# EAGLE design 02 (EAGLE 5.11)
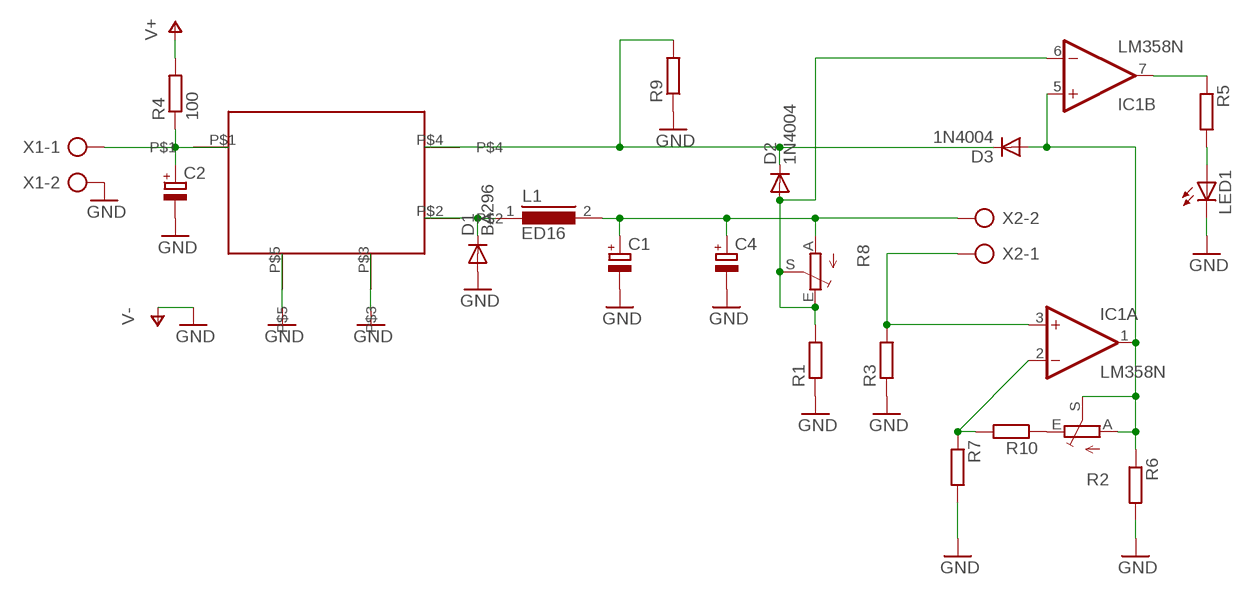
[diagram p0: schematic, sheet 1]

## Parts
C1  CPOL-EUE5-13  [E5-13]
C2  CPOL-EUE5-13  [E5-13]
C4  CPOL-EUE5-13  [E5-13]
D1  BA296  [P2-15]
D2  1N4004  [DO41-10]
D3  1N4004  [DO41-10]
IC1  LM358N  [DIL08]
L1  ED16  [ED16]
LED1  LED3MM  [LED3MM]
R1  R-EU_0207/10  [0207/10]
R2  TRIM_EU-B25P  [B25P]
R3  R-EU_0411/15  [0411/15]
R4  100  R-EU_0207/10  [0207/10]
R5  R-EU_0207/10  [0207/10]
R6  R-EU_0207/10  [0207/10]
R7  R-EU_0207/10  [0207/10]
R8  TRIM_EU-B25P  [B25P]
R9  R-EU_0204/2V  [0204V]
R10  R-EU_0204/7  [0204/7]
U$1  01  [TO220-5_STAGGERED]
X1  AK300/2  [AK300/2]
X2  AK300/2  [AK300/2]

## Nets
N$1: C2.+ R4.1 U$1.P$1 X1.1
N$2: D1.C L1.1 U$1.P$2
N$3: C1.+ C4.+ L1.2 R8.A X2.2
N$4: D2.A IC1.6(B:-IN) R1.2 R8.E R8.S
N$5: IC1.3(A:+IN) R3.2 X2.1
N$6: D2.C D3.C R9.2 U$1.P$4
N$7: IC1.2(A:-IN) R7.1 R10.2
N$8: D3.A IC1.1(A:OUT) IC1.5(B:+IN) R2.A R2.S R6.1
N$9: C1.- C2.- C4.- D1.A LED1.K(C) R1.1 R3.1 R6.2 R7.2 R9.1 U$1.P$3 U$1.P$5 X1.2 ; supply symbol labelled GND
N$10: IC1.7(B:OUT) R5.1
N$11: LED1.A R5.2
N$12: R2.E R10.1
V+: R4.2

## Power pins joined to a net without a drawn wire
N$9: IC1.4(P:V-)
V+: IC1.8(P:V+)

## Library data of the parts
C1 C2 C4 = resistor:CPOL-EU: POLARIZED CAPACITOR, European symbol
D1 = diode:BA296: DIODE
D2 D3 = diode:1N4004: DIODE
IC1 = linear:LM358: OP AMP also LM158; LM258; LM2904 Source: http://cache.national.com/ds/LM/LM158.pdf
L1 = inductors:ED16: INDUCTOR
LED1 = led:LED: LED
R1 R3-R7 R9 R10 = resistor:R-EU_: RESISTOR, European symbol
R2 R8 = pot:TRIM_EU-: POTENTIOMETER
U$1 = to220-my:01
X1 X2 = con-ptr500:AK300/2: CONNECTOR; OC_FARNELL: unknown; OC_NEWARK: unknown

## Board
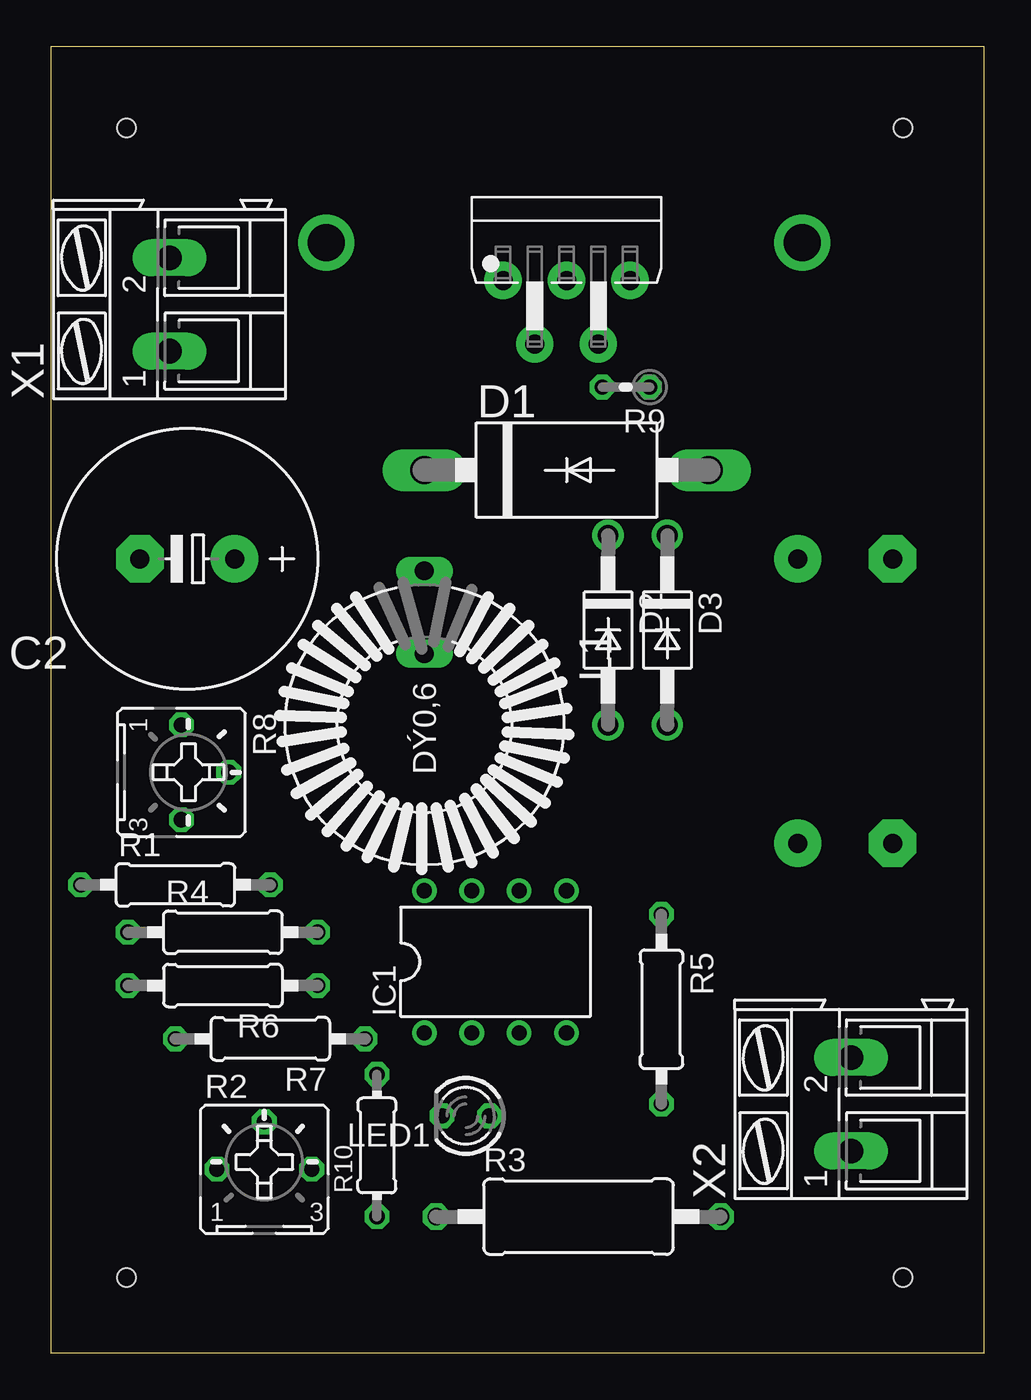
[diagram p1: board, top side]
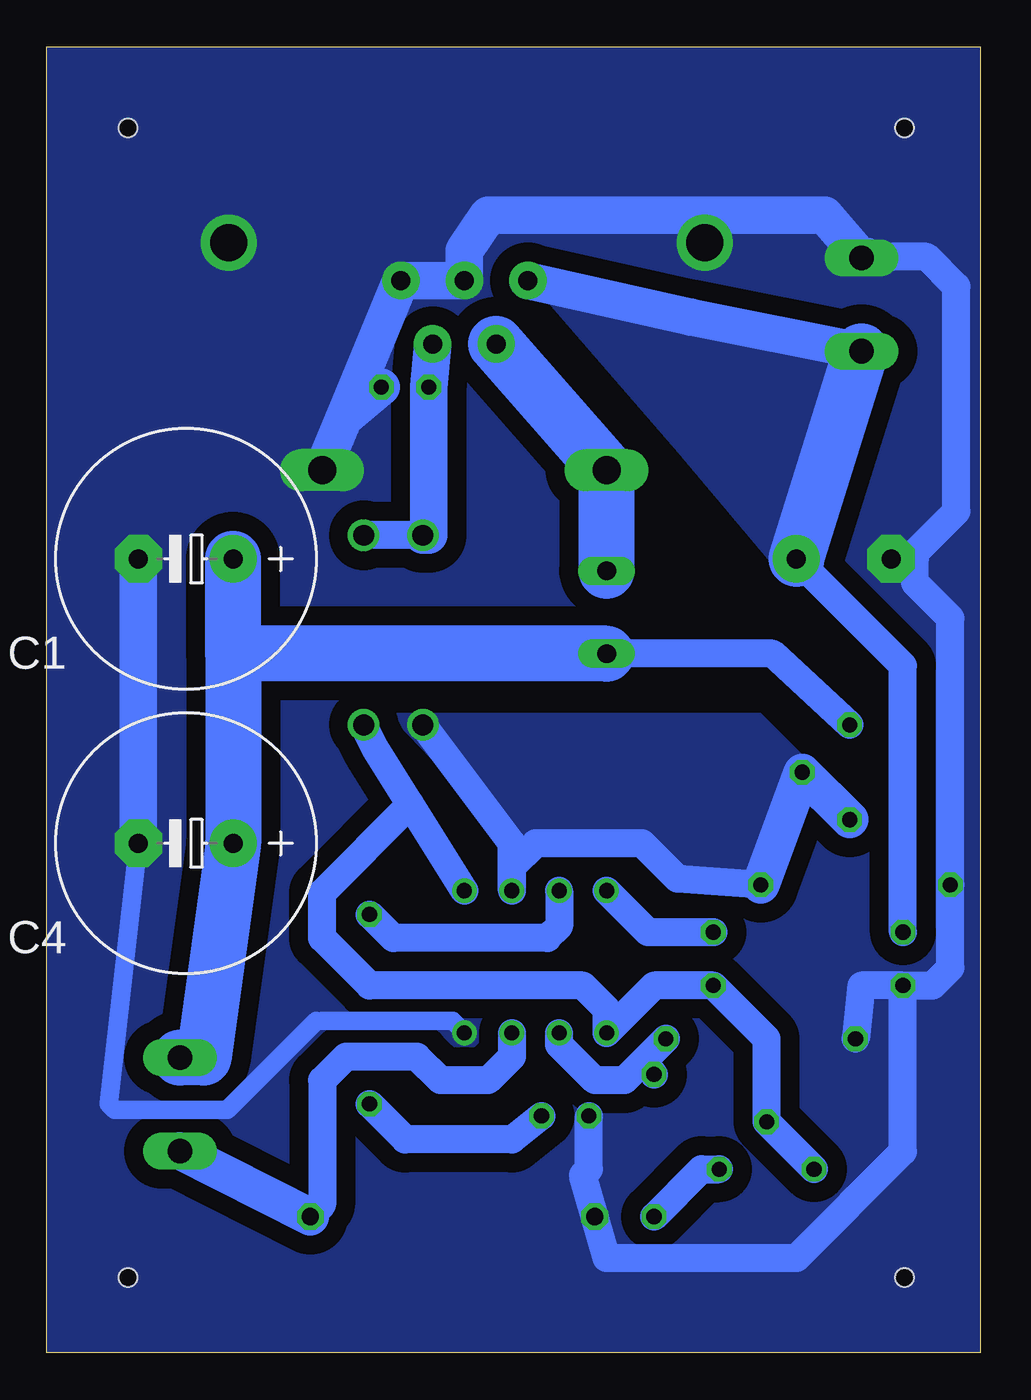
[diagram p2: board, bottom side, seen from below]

Size 50 x 70 mm. Coordinates in mm from the lower left corner, seen from the top.
Outline: 0,0 50,0 50,70 0,70 0,0
Copper layers (1*16): Top 0.035mm / dielectric 1.5mm / Bottom 0.035mm
Design rules "default *": minimum track width 20mil, minimum drill 20mil, track to track 40mil, track to pad 40mil, pad to pad 40mil, via to via 40mil, smd to smd 40mil, copper to edge 0mil, drill to drill 8mil, minimum pad ring 10mil, minimum via ring 8mil, stop-mask expansion 4mil, vias tented up to drill 0mil, thermal gap 0mil
Holes 1 mm at 45.64,4.05 4.05,4.05 4.05,65.64 45.64,65.64

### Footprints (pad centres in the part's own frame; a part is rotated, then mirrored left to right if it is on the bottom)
E5-13 = drill 1.016 pad 2.54 round: + -2.54,0 | drill 1.016 pad 2.54 octagon: - 2.54,0
P2-15 = drill 1.499 long: A 7.62,0; C -7.62,0
DO41-10 = drill 1.118 round: A 5.08,0; C -5.08,0
DIL08 = drill 0.813 pad 1.27 round: 1 -3.81,-3.81; 2 -1.27,-3.81; 3 1.27,-3.81; 4 3.81,-3.81; 5 3.81,3.81; 6 1.27,3.81; 7 -1.27,3.81; 8 -3.81,3.81
ED16 = drill 1.016 long: 1 -8.255,0; 2 -3.81,0
LED3MM = drill 0.813 octagon: A -1.27,0; K 1.27,0
0207/10 = drill 0.813 octagon: 1 -5.08,0; 2 5.08,0
B25P = drill 0.813 octagon: A -2.54,0; E 2.54,0; S 0,2.54
0411/15 = drill 0.914 octagon: 1 -7.62,0; 2 7.62,0
0204V = drill 0.813 octagon: 1 -1.27,0; 2 1.27,0
0204/7 = drill 0.813 octagon: 1 -3.81,0; 2 3.81,0
TO220-5_STAGGERED = drill 1.016 pad 2 round: P$1 -3.402,0; P$2 -1.704,-3.404; P$3 -0.002,0; P$4 1.7,-3.404; P$5 3.402,0
AK300/2 = drill 1.321 long: 1 -2.515,0; 2 2.489,0

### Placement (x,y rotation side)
C1  42.55,42.55 180 bottom
C2  7.3,42.55 180 top
C4  42.55,27.3 180 bottom
D1  27.62,47.31 0 top
D2  29.84,38.73 270 top
D3  33.02,38.73 270 top
IC1  23.81,20.95 0 top
L1  20,33.66 270 top
LED1  22.23,12.7 180 top
R1  6.67,25.08 0 top
R2  11.43,9.84 0 top
R3  28.26,7.3 0 top
R4  9.21,22.54 0 top
R5  32.7,18.41 270 top
R6  9.21,19.68 180 top
R7  11.75,16.83 180 top
R8  6.99,31.11 270 top
R9  30.8,51.75 180 top
R10  17.46,11.11 90 top
U$1  27.62,57.47 0 top
X1  6.35,56.2 90 top
X2  42.86,13.34 90 top

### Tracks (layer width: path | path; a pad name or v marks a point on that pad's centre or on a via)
N$1
  Bottom 1.5: R4.1 4.13,36.83 C2.+
  Bottom 2: X1.1 15.5,55.5 U$1.P$1
  Bottom 3: C2.+ X1.1
  pour Bottom: 11.11,42.23 16.19,48.26 23.5,56.7 7.12,53.2
N$2
  Bottom 3: U$1.P$2 D1.C L1.1
N$3
  Bottom 1.5: R8.A 11.11,37.47 L1.2
  Bottom 3: 40.01,37.47 C4.+ 41.59,15.82 X2.2 | 40.01,37.47 C1.+ | L1.2 40.01,37.47
N$4
  Bottom 1.5: R1.2 16.19,25.4 18.1,27.3 23.81,27.3 25.08,26.04 IC1.6 25.08,27.3 D2.A
  Bottom 2: R8.E R8.S R1.2
  pour Bottom: 9.21,31.75 11.75,34.29 31.75,34.29 24.77,26.99 18.41,26.99 15.88,25.4 11.43,25.4
N$5
  Bottom 1.5: IC1.3 25.08,15.88 26.35,14.61 28.89,14.61 30.16,15.88 33.97,15.88 35.24,14.61 35.24,7.94 R3.2
  Bottom 2: R3.2 X2.1
N$6
  Bottom 1.5: D2.C D3.C
  Bottom 2: D2.C 29.53,43.81 R9.2 U$1.P$4
N$7
  Bottom 1.5: 18.1,15.56 R7.1 | 18.1,15.56 19.05,14.61 20.64,14.61 22.54,16.51 IC1.2 | R10.2 18.1,15.56
N$8
  Bottom 1.5: 30.51,29.39 IC1.5 | 30.51,29.39 32.38,32.38 D3.A | R2.A R2.S 11.43,16.83 R6.1 17.46,19.68 IC1.1 20,18.41 21.27,19.68 32.7,19.68 35.24,22.23 35.24,24.66 30.51,29.39
N$9  (via drill 2)
  Bottom 1: 35.56,17.78 40.32,13.02 46.35,13.02 46.67,13.34 C4.- | IC1.4 28.26,17.78 35.24,17.78
  Bottom 1.5: 3.49,42.55 3.49,41.27 1.59,39.37 R1.1 1.59,20.64 2.54,19.68 R6.2 | 5.98,59 X1.2 4.71,58.74 2.86,58.74 1.27,57.15 1.27,45.09 3.49,42.86 3.49,42.55 | 3.49,42.55 C2.- | LED1.K 20.95,9.84 21.27,9.53 R3.1 20,5.08 9.84,5.08 4.13,10.79 R6.2 | R7.2 6.35,19.68 R6.2
  Bottom 2: C4.- C1.- | X1.2 8.31,60.96 26.35,60.96 27.62,59.06 U$1.P$3 U$1.P$5 34.08,50.07 | 34.08,50.07 D1.A | 34.08,50.07 R9.1
  other vias: 14.75,59.5 40.25,59.5
  pour Bottom: 0,70 50,70 50,0 0,0
N$10
  Bottom 1.5: IC1.7 22.54,22.86 23.18,22.23 31.43,22.23 R5.1
N$11
  Bottom 1.5: LED1.A 25.08,11.43 30.8,11.43 R5.2
N$12
  Bottom 1.5: R10.1 14.92,9.84 R2.E
V+
  Bottom 1.5: R4.2 17.78,22.54 IC1.8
